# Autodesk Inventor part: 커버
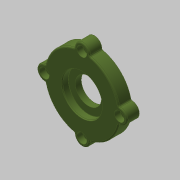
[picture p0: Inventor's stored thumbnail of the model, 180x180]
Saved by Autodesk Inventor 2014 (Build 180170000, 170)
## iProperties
Created: 2016-06
Part Number: 커버
Material: 알루미늄 6061
Document SubType Name: Modeling
Designer: mduedu
Density: 2.71 g/cm^3
Appearance: 올리브 녹색
Author: mduedu
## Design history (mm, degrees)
sketch "스케치1"
  geometry: C1 r 30 at (0, 0); 1 further point
  constraints: 1 centre point, 1 coincident
  dimensions: "d0" = 60 diameter of C1
extrude "돌출1" new body sketch "스케치1" distance "d2" = 10; taper "d3" = 0 deg
sketch "스케치5"
  geometry: C1 r 6 at (0, 30); 2 further points
  constraints: 2 vertical alignment, 1 centre point, 1 other
  dimensions: "d61" = 12 diameter of C1
extrude "돌출3" join sketch "스케치5" stored distance "d62" = 10; taper "d63" = 0 deg
sketch "스케치2"
  geometry: C1 r 21 at (0, 0); 1 further point
  constraints: 1 centre point, 1 coincident
  dimensions: "d4" = 42 diameter of C1
extrude "돌출2" join sketch "스케치2" distance "d6" = 3; taper "d7" = 0 deg
hole "구멍1" diameter "d11" = 35; stored, may be unused: countersink angle "d15" = 90 deg, drill point angle "d17" = 0 deg; dims "d9" = 10, "d10" = 10, "d12" = 6, "d13" = 4, "d14" = 2, "d16" = 3
hole "구멍2" diameter "d20" = 32; stored, may be unused: countersink angle "d24" = 90 deg, drill point angle "d26" = 0 deg; dims "d21" = 6, "d22" = 4, "d23" = 2, "d25" = 5.2, "d67" = 10, "d68" = 10
hole "구멍3" diameter "d29" = 21; stored, may be unused: countersink angle "d33" = 90 deg, drill point angle "d35" = 0 deg; dims "d27" = 10, "d28" = 10, "d30" = 6, "d31" = 4, "d32" = 2, "d34" = 5
fillet "모깎기2" dims "d36" = 3
fillet "모깎기3" dims "d37" = 0.1
chamfer "모따기1" distance "d38" = 0.75; stored, may be unused: second distance "d39" = 2, angle "d40" = 30 deg
chamfer "모따기2" distance "d42" = 0.5; stored, may be unused: second distance "d43" = 2, angle "d44" = 30 deg
sketch "스케치6"
  geometry: A1 r 30 centre (0, 0) between (29.4, 5.97) and (5.97, 29.4) reference; 3 further points
  constraints: 2 vertical alignment, 1 coincident, 3 other
hole "구멍5" sketch "스케치6" at (0, 30) diameter "d69" = 4.5; stored, may be unused: countersink angle "d73" = 90 deg, drill point angle "d75" = 118 deg; dims "d70" = 6, "d71" = 8, "d72" = 4.6, "d74" = 8
fillet "모깎기5" dims "d79" = 1
fillet "모깎기6" dims "d80" = 1
node "솔리드1"
pattern_circular "원형 패턴1" dims angle "d65" = 360 deg
pattern_circular "원형 패턴2" dims angle "d77" = 360 deg
node "투영된 루프1"
